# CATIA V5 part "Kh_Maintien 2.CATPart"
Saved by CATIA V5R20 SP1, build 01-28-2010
Part number: Maintien 2
Bounding box of the stored display mesh (mm): x -31.991 to 31.991, y -32 to 32, z 0 to 7
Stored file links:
  G:\Khaled_CFAO_2011\SIL\SIL_GR1\tmerino\Khaled\CAD_Thinkmotion\Kh_Maintien 2.CATPart
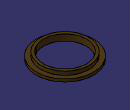
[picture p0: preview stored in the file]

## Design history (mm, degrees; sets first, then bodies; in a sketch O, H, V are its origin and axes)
Body1 (main body)
  Sketch1 on yz-plane, origin (0, 0, 0), H (0, 1, 0), V (0, 0, 1)
    line L1 (24, 7) -> (24, 0)
    line L2 (24, 0) -> (32, 0)
    line L3 (32, 0) -> (32, 3)
    line L4 (32, 3) -> (27, 3)
    line L5 (27, 3) -> (27, 7)
    line L6 (27, 7) -> (24, 7)
    distance V L1 = 24
    distance L1 L5 = 3
    distance L1 L3 = 8
    distance L6 L4 = 4
    distance L4 L2 = 3
    vertical: L1 V, L3 V, L5 V
    horizontal: L2 H, L4 H, L6 H
  Shaft1: profile Sketch1, axis Sketch1.V, angle 360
